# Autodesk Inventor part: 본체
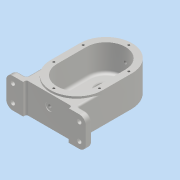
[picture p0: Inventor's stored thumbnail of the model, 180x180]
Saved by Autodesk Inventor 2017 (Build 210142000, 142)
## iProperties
Part Number: 본체
Material: 알루미늄 6061
Document SubType Name: Modeling
Designer: MRC
Density: 2.7 g/cm^3
Appearance: 알루미늄 - 평지
Mass: 756.755 g
Surface Area: 581.829 cm^2
Volume: 280.28 cm^3
Author: MRC
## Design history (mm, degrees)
sketch "스케치1"
  geometry: L1 (0, 0)-(0, -45); L2 (-40, 0)-(-40, -45); L3 (40, -45)-(40, 0); L4 (0, 0)-(0, -45); L5 (-61, -92)-(61, -92); L6 (61, -92)-(61, -82); L7 (61, -82)-(40, -82); L8 (40, -82)-(40, -45); L9 (-61, -92)-(-61, -82); L10 (-61, -82)-(-40, -82); L11 (-40, -82)-(-40, -45); A1 r 40 centre (0, 0) between (40, 0) and (-40, 0); A2 r 40 centre (0, -45) between (-40, -45) and (40, -45); 2 further points
  constraints: 26 end point, 6 point on circle, 4 perpendicular, 4 tangent, 3 parallel, 3 point on line, 2 centre point, 2 midpoint, 1 horizontal, 1 vertical, 1 other
  dimensions: "d0" = 45 distance of L1.start L1.end; "d1" = 80 distance between parallel lines of L3 L2; "d17" = 10 distance of L5.end L6.end; "d18" = 122 distance of L5.start L5.end; "d19" = 92 distance from line of L5 L1.start; "d20" = 37 distance of L10.end L11.end
extrude "돌출1" new body sketch "스케치1" stored distance "d4" = 49; taper "d5" = 0 deg
sketch "스케치2"
  geometry: L1 (0, 0)-(0, -45); L2 (-30, 0)-(-30, -45); L3 (30, -45)-(30, 0); A1 r 40 centre (0, -45) between (-40, -45) and (40, -45) reference; A2 r 40 centre (0, 0) between (40, 0) and (-40, 0) reference; A3 r 30 centre (0, 0) between (30, 0) and (-30, 0); A4 r 30 centre (0, -45) between (-30, -45) and (30, -45); 1 further point
  constraints: 8 end point, 4 point on circle, 4 tangent, 2 centre point, 1 midpoint, 1 parallel, 1 vertical
  dimensions: "d6" = 10 radial gap between concentric circles of A1 A4; "d7" = 30 radius of A3
extrude "돌출2" cut sketch "스케치2" distance "d8" = 41; taper "d9" = 0 deg
sketch "스케치3"
  geometry: L1 (0, 0)-(0, -45); L2 (-26, 0)-(-26, -45); L3 (26, -45)-(26, 0); A1 r 40 centre (0, 0) between (40, 0) and (-40, 0) reference; A2 r 40 centre (0, -45) between (-40, -45) and (40, -45) reference; A3 r 26 centre (0, 0) between (26, 0) and (-26, 0); A4 r 26 centre (0, -45) between (-26, -45) and (26, -45); 1 further point
  constraints: 8 end point, 4 point on circle, 4 tangent, 2 centre point, 1 midpoint, 1 parallel, 1 vertical
  dimensions: "d10" = 52 distance between parallel lines of L3 L2
extrude "돌출3" join sketch "스케치3" distance "d11" = 11; taper "d12" = 0 deg
sketch "스케치4"
  geometry: L1 (-26, 0)-(-26, -45) reference; L2 (26, -45)-(26, 0) reference; L3 (-26, -30)-(26, -30); A1 r 26 centre (0, 0) between (26, 0) and (-26, 0) reference
  constraints: 2 end point, 2 point on line, 1 perpendicular
  dimensions: "d13" = 30 distance from line of A1.centre L3
extrude "돌출4" cut sketch "스케치4" distance "d14" = 3; taper "d15" = 0 deg
sketch "스케치5"
  geometry: L1 (-61, -82)-(-61, -92); L2 (-61, -92)-(61, -92); L3 (61, -92)-(61, -82); L4 (61, -82)-(40, -82); L5 (40, -82)-(40, -45); L6 (-61, -82)-(-40, -82); L7 (-40, -82)-(-40, -45); L8 (0, 0)-(0, -45); A1 r 26 centre (0, 0) between (26, 0) and (-26, 0) reference; A2 r 40 centre (0, 0) between (40, 0) and (-40, 0) reference; A3 r 40 centre (0, -45) between (-40, -45) and (40, -45) reference
  constraints: 16 end point, 5 perpendicular, 2 vertical, 1 horizontal, 1 point on circle, 1 other
  dimensions: "d21" = 122 distance of L1.end L2.end; "d22" = 10 distance of L2.end L3.end; "d23" = 10 distance of L1.start L1.end; "d24" = 92 distance from line of A1.centre L2; "d25" = 37 distance of L4.end L5.end
extrude "돌출5" join sketch "스케치5" distance "d26" = 46; taper "d27" = 0 deg
sketch "스케치6"
  geometry: C1 r 14 at (0, 0); C2 r 11 at (0, 0); A1 r 26 centre (0, 0) between (26, 0) and (-26, 0) reference
  constraints: 2 centre point, 2 coincident
  dimensions: "d28" = 28 diameter of C1; "d29" = 22 diameter of C2
extrude "돌출6" cut sketch "스케치6" distance "d30" = 4; taper "d31" = 0 deg
sketch "스케치7"
  geometry: A1 r 30 centre (0, -45) between (-30, -45) and (30, -45) reference; 1 further point
  constraints: 1 coincident
hole "구멍1" sketch "스케치7" at (0, -45) diameter "d32" = 20; stored, may be unused: countersink angle "d36" = 90 deg, drill point angle "d38" = 0 deg; dims "d33" = 6, "d34" = 28, "d35" = 8, "d37" = 12
sketch "스케치8"
  geometry: C1 r 14 at (0, 0); A1 r 30 centre (0, 0) between (30, 0) and (-30, 0) reference
  constraints: 1 centre point, 1 coincident
  dimensions: "d39" = 28 diameter of C1
extrude "돌출7" cut sketch "스케치8" distance "d40" = 8; taper "d41" = 0 deg
sketch "스케치9"
  geometry: C1 r 14 at (0, 0) reference; C2 r 11 at (0, 0)
  constraints: 1 centre point, 1 coincident
  dimensions: "d42" = 22 diameter of C2
extrude "돌출8" cut sketch "스케치9" stored distance "d43" = 8; taper "d44" = 0 deg
sketch "스케치10"
  geometry: A1 r 30 centre (0, 0) between (30, 0) and (-30, 0) reference; 1 further point
  constraints: 1 vertical alignment
  dimensions: "d45" = 35 distance of A1.centre point (0, 35)
hole "구멍2" sketch "스케치10" at (0, 35) diameter "d46" = 3.242; stored, may be unused: countersink angle "d50" = 90 deg, drill point angle "d52" = 118 deg; dims "d47" = 8, "d48" = 28, "d49" = 8, "d51" = 10
sketch "스케치11"
  geometry: A1 r 30 centre (0, -45) between (-30, -45) and (30, -45) reference; A2 r 30 centre (0, 0) between (30, 0) and (-30, 0) reference; 1 further point
  constraints: 1 vertical alignment
  dimensions: "d56" = 35 distance of A1.centre point (0, -80)
hole "구멍3" sketch "스케치11" at (0, -80) diameter "d57" = 3.242; stored, may be unused: countersink angle "d61" = 90 deg, drill point angle "d63" = 118 deg; dims "d58" = 8, "d59" = 28, "d60" = 8, "d62" = 10
sketch "스케치12"
  geometry: L1 (-61, -92)-(61, -92) reference; L2 (-35, -92)-(35, -92); L3 (35, -92)-(35, -87); L4 (35, -87)-(-35, -87); L5 (-35, -87)-(-35, -92); A1 r 40 centre (0, -45) between (-40, -45) and (40, -45) reference; 2 further points
  constraints: 8 end point, 2 parallel, 1 collinear, 1 horizontal, 1 midpoint, 1 perpendicular, 1 vertical alignment
  dimensions: "d67" = 70 distance between parallel lines of L3 L5; "d68" = 5 distance between parallel lines of L1 L4
extrude "돌출9" cut sketch "스케치12" stored distance "d69" = 8; taper "d70" = 0 deg
sketch "스케치13"
  geometry: C1 r 14 at (0, 0) reference; 1 further point
  constraints: 1 vertical alignment
  dimensions: "d71" = 20 distance of C1.centre point (0, 20)
hole "구멍4" sketch "스케치13" at (0, 20) diameter "d72" = 3.242; stored, may be unused: countersink angle "d76" = 90 deg, drill point angle "d78" = 118 deg; dims "d73" = 8, "d74" = 28, "d75" = 8, "d77" = 10
node "작업 평면1"
sketch "스케치14"
  geometry: L1 (40, 24.5)-(-40, 24.5) reference; C1 r 6 at (0, 3.5); 1 further point
  constraints: 1 centre point, 1 vertical alignment
  dimensions: "d83" = 12 diameter of C1; "d84" = 21 distance from line of L1 C1.centre
extrude "돌출10" join sketch "스케치14" stored distance "d85" = 8; taper "d86" = 0 deg
hole "구멍5" diameter "d89" = 4.917; stored, may be unused: countersink angle "d93" = 90 deg, drill point angle "d95" = 118 deg; dims "d87" = 10, "d88" = 10, "d90" = 12, "d91" = 28, "d92" = 8, "d94" = 17.1
sketch "스케치15"
  geometry: L1 (75, 3)-(-5, 3) reference; C1 r 6 at (35, -18); 1 further point
  constraints: 1 centre point, 1 vertical alignment
  dimensions: "d96" = 12 diameter of C1; "d97" = 21 distance from line of L1 C1.centre
extrude "돌출11" cut sketch "스케치15" distance "d98" = 1; taper "d99" = 0 deg
hole "구멍6" diameter "d102" = 4.917; stored, may be unused: countersink angle "d106" = 90 deg, drill point angle "d108" = 118 deg; dims "d100" = 10, "d101" = 10, "d103" = 12, "d104" = 28, "d105" = 8, "d107" = 17.1
fillet "모깎기1" dims "d109" = 10, "d110" = 3, "d128" = 5
fillet "모깎기2" dims "d111" = 3
sketch "스케치16"
  geometry: C1 r 5.5 at (8, 7); C2 r 3.3 at (8, 7); C3 r 5.5 at (8, 33); C4 r 3.3 at (8, 33); A1 r 7 centre (8, 7) between (8, 0) and (15, 7) reference; A2 r 7 centre (8, 33) between (15, 33) and (8, 40) reference; 1 further point
  constraints: 4 centre point, 4 coincident
  dimensions: "d112" = 11 diameter of C1; "d113" = 6.6 diameter of C2; "d118" = 11 diameter of C3; "d119" = 6.6 diameter of C4
extrude "돌출12" cut sketch "스케치16" distance "d114" = 2; taper "d115" = 0 deg
extrude "돌출13" cut sketch "스케치16" stored distance "d116" = 2; taper "d117" = 0 deg
chamfer "모따기1" distance "d120" = 1; stored, may be unused: second distance "d121" = 2, angle "d122" = 45 deg
fillet "모깎기3" dims "d123" = 3, "d124" = 0.3
sketch "스케치17"
  geometry: L1 (-51, -92)-(-35, -92) reference; A1 r 37 centre (0, 0) between (37, 0) and (-37, 0) reference; 1 further point
  constraints: 1 vertical alignment, 1 other
  dimensions: "d125" = 12 distance from line of L1 point (0, -80)
feature "엠보싱1" sketch "스케치17" dims "d0" = 45, "d1" = 80, "d17" = 10, "d18" = 122, "d19" = 92, "d20" = 37, "d126" = 0.5, "d127" = 0
node "솔리드1"
pattern_circular "원형 패턴1" dims angle "d54" = 180 deg
pattern_circular "원형 패턴2" dims angle "d65" = 180 deg
pattern_circular "원형 패턴3" dims angle "d80" = 360 deg
mirror "미러1"
other parameters: "d82" = 43
